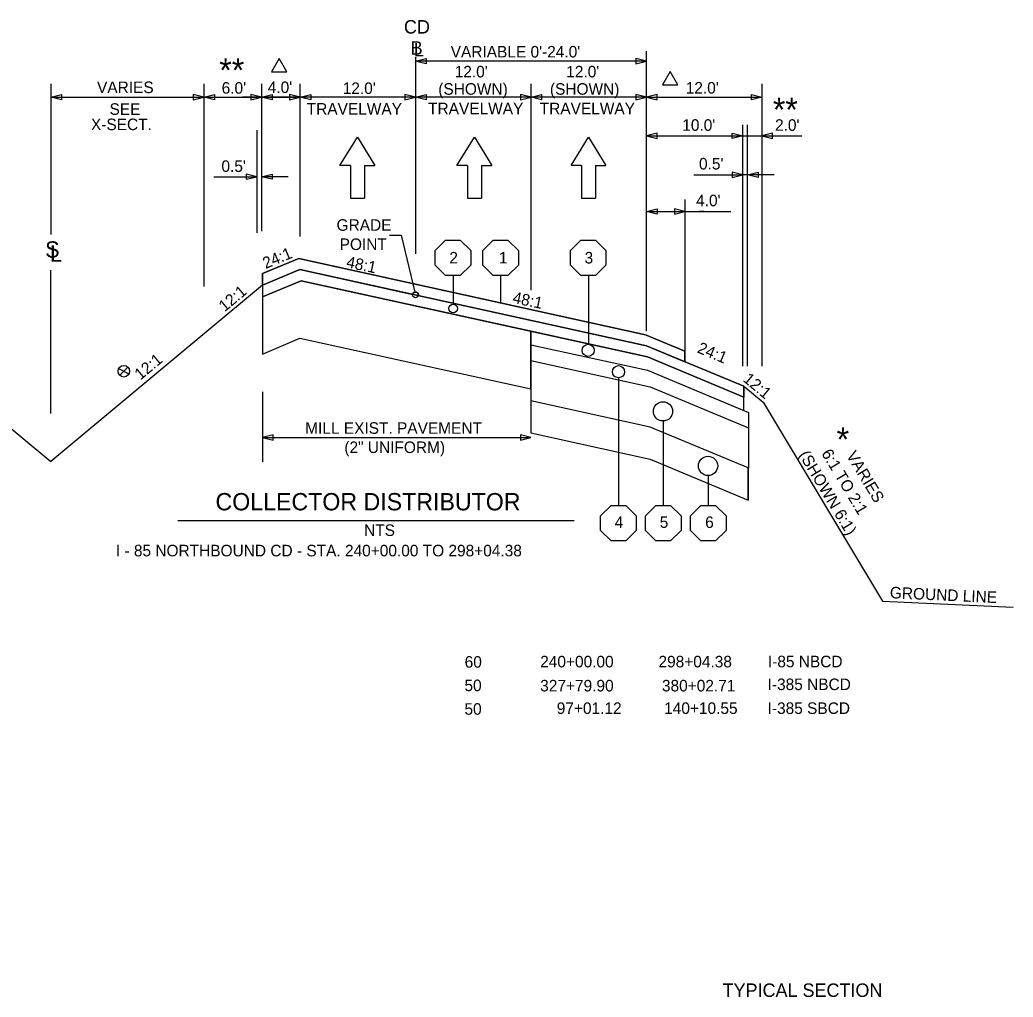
# Model space of a CAD drawing. Extents: x 5017 to 5774, y 4942 to 5266.
# Drawn here: x 5241.5 to 5344.7, y 5012.4 to 5114 of the extents above; entities that cross this region are included whole.
import ezdxf

# ---------------------------------------------------------------- set-up
doc = ezdxf.new("R2010")
doc.units = 0
for name, color, linetype in [('Level 20', 7, 'Continuous'), ('Level 25', 7, 'Continuous'), ('RD_QTY_Surf_Course', 7, 'Continuous'), ('RD_SHT_Typical', 7, 'Continuous'), ('RD_TX_RoadID', 7, 'Continuous'), ('RD_TX_TypSect', 7, 'Continuous'), ('RD_XS_ExGround', 7, 'Continuous'), ('RD_XS_ExPaveRet', 7, 'Continuous'), ('RD_XS_TX_MkPT', 7, 'Continuous'), ('typical_on', 7, 'Continuous')]:
    doc.layers.add(name, color=color, linetype=linetype)

msp = doc.modelspace()

# ---------------------------------------------------------------- linework, layer by layer
at = {"layer": 'Level 20'}
for p, q in [((5274.71, 5098.9), (5276.53, 5101.82)), ((5276.53, 5101.82), (5278.32, 5098.89)), ((5286.87, 5098.9), (5288.7, 5101.82)), ((5288.7, 5101.82), (5290.48, 5098.89)), ((5298.72, 5098.9), (5300.54, 5101.82)), ((5300.54, 5101.82), (5302.33, 5098.89)), ((5275.8, 5098.9), (5274.71, 5098.9)), ((5275.8, 5098.9), (5275.8, 5095.5)), ((5277.26, 5098.89), (5278.32, 5098.89)), ((5277.26, 5098.89), (5277.26, 5095.49)), ((5287.97, 5098.9), (5286.87, 5098.9)), ((5287.97, 5098.9), (5287.97, 5095.5)), ((5289.42, 5098.89), (5290.48, 5098.89)), ((5289.42, 5098.89), (5289.42, 5095.49)), ((5299.81, 5098.9), (5298.72, 5098.9)), ((5299.81, 5098.9), (5299.81, 5095.5)), ((5301.27, 5098.89), (5302.33, 5098.89)), ((5301.27, 5098.89), (5301.27, 5095.49)), ((5275.8, 5095.5), (5277.26, 5095.49)), ((5287.97, 5095.5), (5289.42, 5095.49)), ((5299.81, 5095.5), (5301.27, 5095.49))]:
    msp.add_line(p, q, dxfattribs=at)
at = {"layer": 'RD_QTY_Surf_Course'}
for p, q in [((5270.56, 5088.07), (5266.67, 5086.45)), ((5306.56, 5080.15), (5270.56, 5088.07)), ((5266.67, 5085.24), (5270.67, 5086.91)), ((5266.67, 5086.45), (5266.67, 5085.24)), ((5270.67, 5086.91), (5306.67, 5078.99)), ((5316.67, 5075.94), (5306.56, 5080.15)), ((5306.67, 5078.99), (5316.67, 5074.82)), ((5316.67, 5074.82), (5316.67, 5075.94))]:
    msp.add_line(p, q, dxfattribs=at)
at = {"layer": 'RD_SHT_Typical'}
for p, q in [((5294.56, 5107.37), (5294.56, 5085.94)), ((5270.56, 5088.07), (5266.67, 5086.45)), ((5270.56, 5088.07), (5306.56, 5080.15)), ((5266.67, 5086.45), (5260.67, 5081.45)), ((5270.67, 5086.91), (5266.67, 5085.24)), ((5266.67, 5086.45), (5266.67, 5085.24)), ((5270.67, 5086.91), (5306.67, 5078.99)), ((5225.14, 5084.38), (5244.66, 5068.11)), ((5266.67, 5082.25), (5266.67, 5082.25)), ((5260.67, 5081.45), (5244.66, 5068.11)), ((5294.56, 5080.26), (5294.56, 5081.66)), ((5294.56, 5080.26), (5294.56, 5078.61)), ((5294.56, 5080.26), (5306.67, 5077.6)), ((5294.56, 5080.26), (5306.67, 5077.6)), ((5306.56, 5080.15), (5316.67, 5075.94)), ((5306.67, 5078.99), (5316.67, 5074.82)), ((5294.56, 5078.66), (5294.56, 5078.66)), ((5294.56, 5078.61), (5294.56, 5074.42)), ((5294.56, 5078.61), (5306.96, 5075.88)), ((5306.67, 5077.6), (5316.67, 5073.43)), ((5306.67, 5077.6), (5317.17, 5073.22)), ((5306.96, 5075.88), (5317.17, 5071.62)), ((5316.67, 5075.94), (5318.67, 5074.27)), ((5316.67, 5075.94), (5316.67, 5074.82)), ((5316.67, 5073.43), (5316.67, 5074.82)), ((5294.56, 5074.42), (5294.56, 5071.09)), ((5294.56, 5074.42), (5294.56, 5071.09)), ((5306.93, 5071.7), (5294.56, 5074.42)), ((5318.67, 5074.27), (5331.07, 5053.6)), ((5317.17, 5073.22), (5317.17, 5071.62)), ((5317.14, 5067.45), (5306.93, 5071.7)), ((5294.56, 5071.09), (5306.93, 5068.37)), ((5294.56, 5071.09), (5306.93, 5068.37)), ((5317.17, 5071.62), (5317.17, 5067.43)), ((5306.93, 5068.37), (5317.14, 5064.11)), ((5306.93, 5068.37), (5317.14, 5064.11)), ((5317.14, 5067.45), (5317.14, 5064.11)), ((5317.14, 5064.11), (5317.14, 5067.45))]:
    msp.add_line(p, q, dxfattribs=at)
at = {"layer": 'RD_TX_TypSect'}
for p, q in [((5282.56, 5110.13), (5282.56, 5089.7)), ((5306.56, 5081.66), (5306.56, 5110.76)), ((5306.56, 5109.73), (5282.56, 5109.73)), ((5244.66, 5107.37), (5244.66, 5091.7)), ((5260.56, 5107.37), (5260.56, 5086.3)), ((5266.56, 5107.37), (5266.56, 5092.07)), ((5270.56, 5107.37), (5270.56, 5091.5)), ((5318.56, 5107.37), (5318.56, 5098.73)), ((5244.67, 5106), (5260.57, 5106)), ((5260.57, 5106), (5266.57, 5106)), ((5282.57, 5106), (5264.57, 5106)), ((5266.57, 5106), (5270.57, 5106)), ((5294.57, 5106), (5282.57, 5106)), ((5306.56, 5106), (5294.57, 5106)), ((5306.56, 5106), (5318.56, 5106)), ((5316.56, 5078.02), (5316.56, 5103.12)), ((5317.06, 5078.02), (5317.06, 5103.12)), ((5266.06, 5102.54), (5266.06, 5091.87)), ((5306.56, 5101.96), (5316.56, 5101.96)), ((5316.56, 5101.96), (5318.56, 5101.96)), ((5318.56, 5101.96), (5322.7, 5101.96)), ((5318.56, 5099.49), (5318.56, 5078.02)), ((5261.6, 5097.72), (5266.07, 5097.72)), ((5269.33, 5097.72), (5266.57, 5097.72)), ((5311.47, 5097.92), (5316.56, 5097.92)), ((5319.83, 5097.92), (5316.56, 5097.92)), ((5310.56, 5095.36), (5310.56, 5079.17)), ((5306.56, 5094.09), (5315.32, 5094.09)), ((5312.56, 5094.09), (5312.06, 5094.09)), ((5279.85, 5091.65), (5281.06, 5091.65)), ((5281.06, 5091.65), (5282.49, 5085.72)), ((5266.67, 5087.65), (5270.45, 5089.22)), ((5270.45, 5089.22), (5266.67, 5087.65)), ((5270.45, 5089.22), (5306.45, 5081.3)), ((5306.45, 5081.3), (5270.45, 5089.22)), ((5266.67, 5086.45), (5270.56, 5088.07)), ((5266.67, 5086.45), (5266.67, 5087.65)), ((5266.67, 5087.65), (5266.67, 5086.45)), ((5270.56, 5088.07), (5282.27, 5085.49)), ((5286.48, 5087.45), (5286.48, 5084.48)), ((5291.4, 5087.45), (5291.4, 5084.61)), ((5300.53, 5087.45), (5300.53, 5080.29)), ((5282.85, 5085.36), (5306.56, 5080.15)), ((5306.67, 5078.99), (5294.56, 5081.66)), ((5294.56, 5081.66), (5294.56, 5080.26)), ((5306.45, 5081.3), (5310.56, 5079.59)), ((5310.56, 5079.59), (5306.45, 5081.3)), ((5294.56, 5080.26), (5306.67, 5077.6)), ((5306.56, 5080.15), (5310.56, 5078.48)), ((5316.67, 5074.82), (5306.67, 5078.99)), ((5310.56, 5079.59), (5310.56, 5078.48)), ((5251.84, 5077.08), (5252.66, 5077.92)), ((5251.71, 5077.77), (5252.79, 5077.22)), ((5303.65, 5076.82), (5303.65, 5063.55)), ((5306.67, 5077.6), (5316.67, 5073.43)), ((5266.67, 5075.36), (5266.67, 5068.1)), ((5316.67, 5073.43), (5316.67, 5074.82)), ((5308.28, 5072.33), (5308.28, 5063.55)), ((5312.96, 5066.66), (5312.96, 5063.55)), ((5257.88, 5061.99), (5299.04, 5061.99))]:
    msp.add_line(p, q, dxfattribs=at)
for points in [[(5268.39, 5110.02), (5267.59, 5108.63), (5269.19, 5108.63)], [(5283.66, 5110), (5283.66, 5109.45), (5282.56, 5109.73)], [(5305.46, 5110), (5305.46, 5109.45), (5306.56, 5109.73)], [(5309.03, 5108.64), (5308.23, 5107.26), (5309.83, 5107.26)], [(5245.77, 5106.27), (5245.77, 5105.72), (5244.67, 5106)], [(5259.46, 5106.27), (5259.46, 5105.72), (5260.57, 5106)], [(5261.67, 5106.27), (5261.67, 5105.72), (5260.57, 5106)], [(5265.46, 5106.27), (5265.46, 5105.72), (5266.57, 5106)], [(5267.67, 5106.27), (5267.67, 5105.72), (5266.57, 5106)], [(5269.46, 5106.27), (5269.46, 5105.72), (5270.57, 5106)], [(5271.67, 5106.27), (5271.67, 5105.72), (5270.57, 5106)], [(5281.46, 5106.27), (5281.46, 5105.72), (5282.57, 5106)], [(5283.67, 5106.27), (5283.67, 5105.72), (5282.57, 5106)], [(5293.46, 5106.27), (5293.46, 5105.72), (5294.57, 5106)], [(5295.67, 5106.27), (5295.67, 5105.72), (5294.57, 5106)], [(5305.46, 5106.27), (5305.46, 5105.72), (5306.56, 5106)], [(5307.66, 5105.72), (5307.66, 5106.27), (5306.56, 5106)], [(5317.46, 5105.72), (5317.46, 5106.27), (5318.56, 5106)], [(5307.66, 5101.68), (5307.66, 5102.23), (5306.56, 5101.96)], [(5315.46, 5101.68), (5315.46, 5102.23), (5316.56, 5101.96)], [(5319.66, 5101.68), (5319.66, 5102.23), (5318.56, 5101.96)], [(5264.96, 5098), (5264.96, 5097.45), (5266.07, 5097.72)], [(5267.67, 5098), (5267.67, 5097.45), (5266.57, 5097.72)], [(5315.46, 5098.19), (5315.46, 5097.64), (5316.56, 5097.92)], [(5318.16, 5098.19), (5318.16, 5097.64), (5317.06, 5097.92)], [(5307.66, 5094.37), (5307.66, 5093.82), (5306.56, 5094.09)], [(5309.46, 5094.37), (5309.46, 5093.82), (5310.56, 5094.09)], [(5267.77, 5070.33), (5267.77, 5070.88), (5266.67, 5070.61)], [(5293.46, 5070.88), (5293.46, 5070.33), (5294.56, 5070.61)]]:
    msp.add_lwpolyline(points, close=True, dxfattribs=at)
msp.add_lwpolyline([(5310.56, 5078.48), (5310.56, 5079.17), (5310.56, 5079.59)], dxfattribs=at)
for centre, radius in [((5282.56, 5085.43), 0.3), ((5286.48, 5084.02), 0.459), ((5300.5, 5079.67), 0.63), ((5252.26, 5077.5), 0.6), ((5303.65, 5077.45), 0.63), ((5308.28, 5073.33), 1), ((5312.96, 5067.66), 1)]:
    msp.add_circle(centre, radius, dxfattribs=at)
msp.add_arc((5282.56, 5085.43), 0.3, 347.5943, 167.5943, dxfattribs=at)
at = {"layer": 'RD_XS_ExGround'}
for p, q in [((5266.67, 5070.61), (5294.56, 5070.61)), ((5331.07, 5053.6), (5344.66, 5052.98))]:
    msp.add_line(p, q, dxfattribs=at)
at = {"layer": 'RD_XS_ExPaveRet'}
for p, q in [((5266.67, 5085.24), (5266.67, 5085.24)), ((5266.67, 5085.24), (5266.67, 5079.26)), ((5266.67, 5079.26), (5270.56, 5080.95)), ((5270.56, 5080.95), (5294.56, 5075.68)), ((5294.56, 5080.06), (5294.56, 5081.66)), ((5294.56, 5078.41), (5294.56, 5080.06)), ((5294.56, 5075.68), (5294.56, 5078.41))]:
    msp.add_line(p, q, dxfattribs=at)
msp.add_lwpolyline([(5294.56, 5081.66), (5270.67, 5086.91), (5266.67, 5085.24)], dxfattribs=at)
at = {"layer": 'RD_XS_TX_MkPT'}
for p, q in [((5244.66, 5078.12), (5244.66, 5088.01)), ((5244.66, 5073.12), (5244.66, 5078.12))]:
    msp.add_line(p, q, dxfattribs=at)
at = {"layer": 'typical_on'}
for points in [[(5288.3, 5090.06), (5288.3, 5088.53), (5287.22, 5087.45), (5285.69, 5087.45), (5284.61, 5088.53), (5284.61, 5090.06), (5285.69, 5091.14), (5287.22, 5091.14)], [(5293.25, 5090.06), (5293.25, 5088.53), (5292.17, 5087.45), (5290.64, 5087.45), (5289.55, 5088.53), (5289.55, 5090.06), (5290.64, 5091.14), (5292.17, 5091.14)], [(5302.35, 5090.06), (5302.35, 5088.53), (5301.27, 5087.45), (5299.74, 5087.45), (5298.66, 5088.53), (5298.66, 5090.06), (5299.74, 5091.14), (5301.27, 5091.14)], [(5305.49, 5062.47), (5305.49, 5060.94), (5304.41, 5059.86), (5302.88, 5059.86), (5301.8, 5060.94), (5301.8, 5062.47), (5302.88, 5063.55), (5304.41, 5063.55)], [(5310.15, 5062.47), (5310.15, 5060.94), (5309.07, 5059.86), (5307.54, 5059.86), (5306.46, 5060.94), (5306.46, 5062.47), (5307.54, 5063.55), (5309.07, 5063.55)], [(5314.84, 5062.47), (5314.84, 5060.94), (5313.75, 5059.86), (5312.22, 5059.86), (5311.14, 5060.94), (5311.14, 5062.47), (5312.22, 5063.55), (5313.75, 5063.55)]]:
    msp.add_lwpolyline(points, close=True, dxfattribs=at)

# ---------------------------------------------------------------- texts
at = {"layer": 'Level 25'}
for s, p in [('GRADE', (5274.36, 5092.1)), ('POINT', (5274.68, 5090.1))]:
    msp.add_text(s, height=1.2, dxfattribs=at).set_placement(p)
at = {"layer": 'RD_TX_RoadID'}
msp.add_text('TYPICAL SECTION', height=1.3967, dxfattribs=at).set_placement((5314.47, 5012.47))
at = {"layer": 'RD_TX_TypSect'}
for s, height, p in [('CD', 1.4, (5281.36, 5112.6)), ('B', 1.4, (5282.06, 5110.4)), ('L', 1.4, (5282.39, 5110.22)), ("VARIABLE 0'-24.0'", 1.2, (5286.22, 5110.11)), ('**', 2.5, (5262.17, 5107.54)), (" 12.0'", 1.2, (5286.19, 5108.04)), (" 12.0'", 1.2, (5297.78, 5108.04)), ('VARIES', 1.2, (5249.47, 5106.41)), ("6.0'", 1.2, (5262.42, 5106.35)), ("4.0'", 1.2, (5267.21, 5106.42)), ("12.0'", 1.2, (5275, 5106.32)), ('(SHOWN)', 1.2, (5284.93, 5106.24)), ('(SHOWN)', 1.2, (5296.53, 5106.24)), ("12.0'", 1.2, (5310.64, 5106.36)), ('**', 2.5, (5319.69, 5103.44)), ('SEE', 1.2, (5250.77, 5104.15)), ('TRAVELWAY', 1.2, (5271.26, 5104.17)), ('TRAVELWAY', 1.2, (5283.87, 5104.21)), ('TRAVELWAY', 1.2, (5295.47, 5104.21)), ('X-SECT.', 1.2, (5248.84, 5102.56)), ("10.0'", 1.2, (5310.28, 5102.49)), ("2.0'", 1.2, (5319.92, 5102.49)), ("0.5'", 1.2, (5312.02, 5098.47)), ("0.5'", 1.2, (5262.4, 5098.22)), ("4.0'", 1.2, (5311.72, 5094.65)), ('2', 1.2, (5286.08, 5088.7)), ('1', 1.2, (5291.23, 5088.7)), ('3', 1.2, (5300.13, 5088.7)), ('MILL EXIST. PAVEMENT', 1.2, (5271.1, 5071)), ('*', 2.5, (5326.32, 5069.17)), ('(2" UNIFORM)', 1.2, (5275.17, 5069)), ('COLLECTOR DISTRIBUTOR', 1.8, (5261.78, 5063.04)), ('4', 1.2, (5303.26, 5061.22)), ('5', 1.2, (5307.94, 5061.22)), ('6', 1.2, (5312.66, 5061.21)), ('NTS', 1.2, (5277.22, 5060.38)), ('I - 85 NORTHBOUND CD - STA. 240+00.00 TO 298+04.38', 1.2, (5251.43, 5058.26)), ('60', 1.2, (5287.67, 5046.69)), ('240+00.00', 1.2, (5295.52, 5046.72)), ('298+04.38', 1.2, (5307.81, 5046.72)), ('I-85 NBCD', 1.2, (5319.18, 5046.73)), ('50', 1.2, (5287.65, 5044.25)), ('327+79.90', 1.2, (5295.52, 5044.22)), ('380+02.71', 1.2, (5308.17, 5044.22)), ('I-385 NBCD', 1.2, (5319.15, 5044.36)), ('50', 1.2, (5287.65, 5041.8)), ('97+01.12', 1.2, (5297.24, 5041.88)), ('140+10.55', 1.2, (5308.4, 5041.88)), ('I-385 SBCD', 1.2, (5319.15, 5041.88))]:
    msp.add_text(s, height=height, dxfattribs=at).set_placement(p)
for s, rotation, p in [('24:1', 22.6199, (5266.98, 5088.12)), ('48:1', 348.2317, (5275.3, 5088.31)), ('12:1', 39.8056, (5262.73, 5083.62)), ('48:1', 348.2317, (5292.58, 5084.61)), ('24:1', 337.3801, (5311.75, 5079.48)), ('12:1', 39.8056, (5253.98, 5076.53)), ('12:1', 320.1944, (5316.51, 5076.53)), ('(SHOWN 6:1)', 300.9638, (5322.35, 5068.81)), ('6:1 TO 2:1', 300.9638, (5324.7, 5068.97)), ('VARIES', 300.9638, (5327.28, 5068.76)), ('GROUND LINE', 357.3905, (5331.83, 5053.91))]:
    msp.add_text(s, height=1.2, rotation=rotation, dxfattribs=at).set_placement(p)
at = {"layer": 'RD_XS_TX_MkPT'}
for s, p in [('S', (5244.08, 5089.32)), ('L', (5244.59, 5088.89))]:
    msp.add_text(s, height=1.68, dxfattribs=at).set_placement(p)

doc.saveas('drawing.dxf')
